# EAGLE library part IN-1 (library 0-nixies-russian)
IN-1: large numeric topview nixie tube
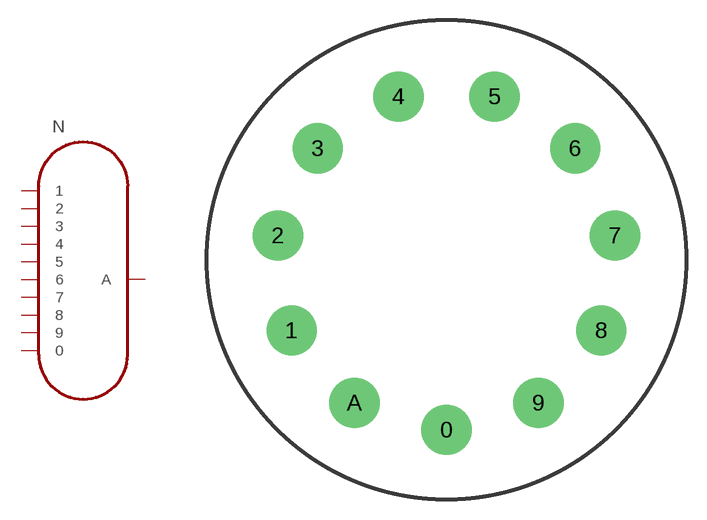
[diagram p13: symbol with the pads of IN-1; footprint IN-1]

Designator prefix N

## IN-1  [IN-1]
0  0
1  1
2  2
3  3
4  4
5  5
6  6
7  7
8  8
9  9
A  A

## Footprint IN-1 (pad centres in mm)
May be used with socket: U11
drill 2.667 round: 0 0,-12.483; 1 -11.355,-5.186; 2 -12.356,1.776; 3 -9.434,8.175; 4 -3.517,11.977; 5 3.517,11.977; 6 9.434,8.175; 7 12.356,1.776; 8 11.355,-5.186; 9 6.749,-10.501; A -6.749,-10.501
